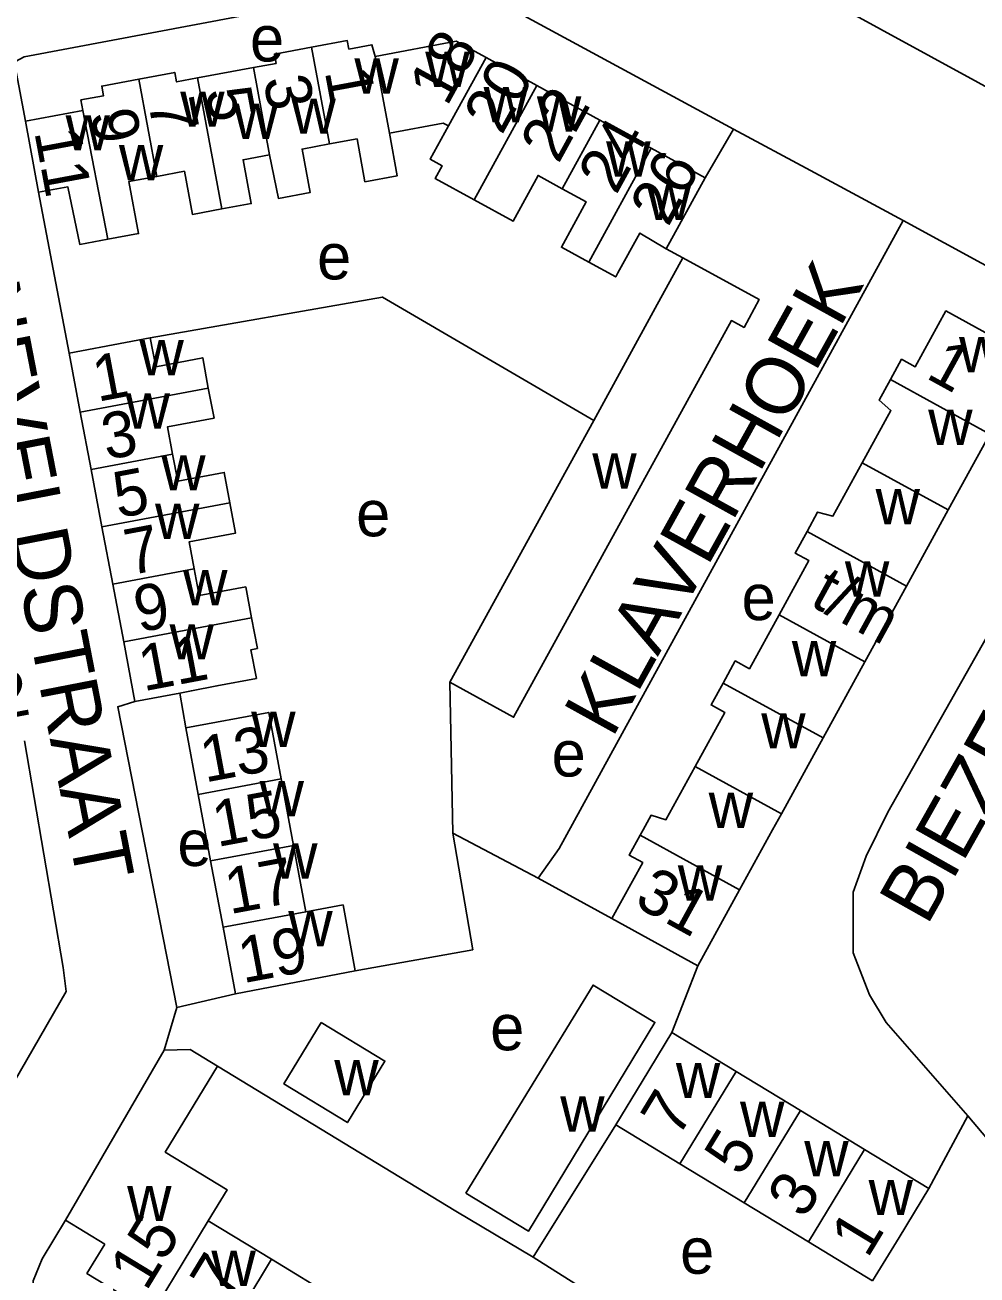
# Model space of a CAD drawing. Extents: x 158356 to 159894, y 383831 to 385260.
# Drawn here: x 158810.6 to 158893.5, y 383961.2 to 384070.1 of the extents above; entities that cross this region are included whole.
import ezdxf

# ---------------------------------------------------------------- set-up
doc = ezdxf.new("R2010")
doc.units = 0
for name, color, linetype in [('BLT_Basislijn', 7, 'Continuous'), ('BLT_Bebouwing', 7, 'Continuous'), ('BLT_Centroide', 7, 'Continuous'), ('BLT_Huisnummer', 7, 'Continuous'), ('BLT_Huisnummer_ tussenligend', 7, 'Continuous'), ('BLT_Huisnummer_reeks', 7, 'Continuous'), ('BLT_Onderverdeling_panden', 7, 'Continuous'), ('BLT_Straatnaam', 7, 'Continuous')]:
    doc.layers.add(name, color=color, linetype=linetype)

msp = doc.modelspace()

# ---------------------------------------------------------------- linework, layer by layer
at = {"layer": 'BLT_Basislijn'}
for p, q in [((158869.84, 384056.78), (158872.31, 384061.02)), ((158811.81, 384055.53), (158814.46, 384041.51)), ((158867.92, 384049.82), (158866.45, 384050.61)), ((158847.88, 383999.71), (158847.63, 384012.86)), ((158824.1, 384011.92), (158824.63, 384008.88)), ((158813.96, 383988.01), (158810.59, 384007.75)), ((158847.88, 383999.71), (158855.3, 383995.79)), ((158855.3, 383995.79), (158861.73, 383992.28)), ((158866.95, 383982.37), (158869.22, 383988.17)), ((158823.85, 383984.52), (158828.95, 383985.73)), ((158823.85, 383984.52), (158822.73, 383980.82)), ((158892.73, 383975.11), (158889.32, 383968.77)), ((158892.73, 383975.11), (158900.43, 383965.89)), ((158862.06, 383974.33), (158854.87, 383962.79)), ((158877.21, 383948.71), (158854.87, 383962.79))]:
    msp.add_line(p, q, dxfattribs=at)
for points in [[(158833.44, 384117.69), (158855.2, 384086.11), (158906.53, 384058.02)], [(158810.66, 384061.72), (158809.81, 384066.33), (158809.81, 384066.91), (158810.54, 384067.32), (158847.76, 384074.35)], [(158847.76, 384074.35), (158872.31, 384061.02)], [(158887.08, 384053.08), (158879.02, 384057.42), (158872.31, 384061.02)], [(158887.08, 384053.08), (158857.13, 383998.39), (158855.3, 383995.79)], [(158887.08, 384053.08), (158904.3, 384043.68), (158905.57, 384042.39), (158906.53, 384040.81), (158906.21, 384037.78), (158885.76, 384001.55), (158883.87, 383997.72), (158882.73, 383994.59), (158882.73, 383989.28), (158884.17, 383985.63), (158885.61, 383983.23), (158892.73, 383975.11)], [(158860.15, 384035.66), (158841.75, 384046.4), (158821.53, 384042.85)], [(158820.2, 384011.18), (158818.71, 384010.73), (158823.85, 383984.52)], [(158847.88, 383999.71), (158849.62, 383989.56), (158839.39, 383987.72)], [(158759.91, 383992.3), (158798.47, 383965.97), (158799.62, 383965.5), (158801.69, 383965.58), (158803.35, 383967.13), (158814.2, 383985.93), (158813.96, 383988.01)], [(158827.39, 383979.43), (158848.13, 383966.79), (158854.87, 383962.79)], [(158814.16, 383966.01), (158812.13, 383962.64), (158811.34, 383960.74), (158811.34, 383959.69), (158812.63, 383957.28), (158815.24, 383955.2), (158828.49, 383947.37), (158863.52, 383925.87)]]:
    msp.add_lwpolyline(points, dxfattribs=at)
at = {"layer": 'BLT_Bebouwing'}
for p, q in [((158850.77, 384067.26), (158855.2, 384064.82)), ((158825.65, 384065.48), (158830.53, 384066.38)), ((158855.2, 384064.82), (158860.68, 384061.81)), ((158810.66, 384061.72), (158815.66, 384062.65)), ((158860.68, 384061.81), (158865.14, 384059.36)), ((158811.81, 384055.53), (158810.66, 384061.72)), ((158865.14, 384059.36), (158869.84, 384056.78)), ((158869.84, 384056.78), (158866.45, 384050.61)), ((158815.43, 384036.37), (158814.46, 384041.51)), ((158816.38, 384031.38), (158815.43, 384036.37)), ((158860.15, 384035.66), (158847.63, 384012.86)), ((158894.65, 384034.47), (158891.02, 384027.86)), ((158817.33, 384026.38), (158816.38, 384031.38)), ((158891.02, 384027.86), (158887.39, 384021.24)), ((158818.27, 384021.39), (158817.33, 384026.38)), ((158819.22, 384016.37), (158818.27, 384021.39)), ((158887.39, 384021.24), (158883.75, 384014.63)), ((158820.2, 384011.18), (158819.22, 384016.37)), ((158883.75, 384014.63), (158880.12, 384008.01)), ((158824.1, 384011.92), (158820.2, 384011.18)), ((158825.71, 384003.09), (158824.63, 384008.88)), ((158880.12, 384008.01), (158876.49, 384001.4)), ((158832.93, 384004.44), (158834.01, 383998.65)), ((158825.71, 384003.09), (158826.79, 383997.31)), ((158834.01, 383998.65), (158835.09, 383992.86)), ((158827.87, 383991.52), (158826.79, 383997.31)), ((158872.85, 383994.78), (158869.22, 383988.17)), ((158869.22, 383988.17), (158861.73, 383992.28)), ((158828.95, 383985.73), (158827.87, 383991.52)), ((158839.39, 383987.72), (158828.95, 383985.73)), ((158866.95, 383982.37), (158872.55, 383978.97)), ((158822.73, 383980.82), (158814.16, 383966.01)), ((158872.55, 383978.97), (158878.14, 383975.57)), ((158878.14, 383975.57), (158883.73, 383972.17)), ((158867.66, 383970.93), (158862.06, 383974.33)), ((158883.73, 383972.17), (158889.32, 383968.77)), ((158873.25, 383967.53), (158867.66, 383970.93)), ((158878.84, 383964.13), (158873.25, 383967.53)), ((158814.16, 383966.01), (158817.58, 383963.93)), ((158826.59, 383965.95), (158832.09, 383962.61)), ((158884.43, 383960.73), (158878.84, 383964.13)), ((158832.09, 383962.61), (158837.69, 383959.2))]:
    msp.add_line(p, q, dxfattribs=at)
for points in [[(158835.58, 384068.16), (158838.69, 384068.74), (158838.83, 384068), (158840.83, 384068.38), (158841.11, 384067.36)], [(158841.11, 384067.36), (158848.18, 384068.68), (158850.77, 384067.26)], [(158830.53, 384066.38), (158832.49, 384066.75), (158832.34, 384067.56), (158835.58, 384068.16)], [(158815.66, 384062.65), (158815.49, 384063.57), (158817.47, 384063.93), (158817.31, 384064.78), (158820.53, 384065.37)], [(158820.53, 384065.37), (158823.67, 384065.96), (158823.82, 384065.14), (158825.65, 384065.48)], [(158842.36, 384060.67), (158843.04, 384056.97), (158840.23, 384056.45), (158839.54, 384060.18), (158837.14, 384059.74)], [(158847.51, 384061.31), (158847.05, 384061.55), (158842.36, 384060.67)], [(158849.74, 384054.86), (158846.35, 384056.72), (158846.96, 384057.83), (158845.92, 384058.4), (158847.51, 384061.31)], [(158837.14, 384059.74), (158834.75, 384059.29), (158835.46, 384055.51), (158832.69, 384054.99), (158831.93, 384058.79)], [(158831.93, 384058.79), (158829.61, 384058.36), (158830.32, 384054.55), (158827.76, 384054.08)], [(158822.1, 384056.91), (158819.68, 384056.47), (158820.52, 384051.93), (158817.84, 384051.44)], [(158827.76, 384054.08), (158825.21, 384053.6), (158824.51, 384057.36), (158822.1, 384056.91)], [(158857.41, 384055.84), (158855.31, 384056.99), (158853.13, 384053.01), (158849.74, 384054.86)], [(158817.84, 384051.44), (158815.4, 384050.99), (158814.36, 384056), (158811.81, 384055.53)], [(158859.71, 384049.45), (158857.34, 384050.74), (158859.5, 384054.69), (158857.41, 384055.84)], [(158866.45, 384050.61), (158864.17, 384051.97), (158862.26, 384048.5), (158862.07, 384048.15), (158859.71, 384049.45)], [(158847.63, 384012.86), (158848.79, 384012.22), (158853.17, 384009.81), (158872.13, 384044.36), (158873.24, 384043.76), (158874.56, 384046.18), (158867.92, 384049.82)], [(158867.92, 384049.82), (158865.51, 384045.44), (158860.15, 384035.66)], [(158885.99, 384039.23), (158886.96, 384040.99), (158888.14, 384040.34), (158890.81, 384045.19), (158898.29, 384041.08), (158894.65, 384034.47)], [(158814.46, 384041.51), (158819.37, 384042.44), (158821.53, 384042.85)], [(158821.53, 384042.85), (158822.01, 384040.34), (158826.1, 384041.11), (158826.59, 384038.48)], [(158883.52, 384031.98), (158886.02, 384036.51), (158885, 384037.42), (158885.99, 384039.23)], [(158826.59, 384038.48), (158827.09, 384035.86), (158823.03, 384035.09), (158823.48, 384032.72)], [(158823.48, 384032.72), (158823.92, 384030.36), (158827.97, 384031.13), (158828.47, 384028.49)], [(158878.72, 384026), (158879.63, 384027.67), (158880.97, 384027.33), (158883.52, 384031.98)], [(158828.47, 384028.49), (158828.97, 384025.85), (158824.91, 384025.08), (158825.36, 384022.74)], [(158876.29, 384018.73), (158878.88, 384023.46), (158877.68, 384024.11), (158878.72, 384026)], [(158825.36, 384022.74), (158825.8, 384020.4), (158829.85, 384021.16), (158830.36, 384018.48)], [(158830.36, 384018.48), (158830.87, 384015.8), (158830.3, 384015.69), (158830.77, 384013.19), (158827.34, 384012.54), (158825.12, 384012.12), (158824.1, 384011.92)], [(158871.42, 384012.79), (158872.47, 384014.71), (158873.7, 384014.03), (158876.29, 384018.73)], [(158868.99, 384005.52), (158871.57, 384010.22), (158870.37, 384010.88), (158871.42, 384012.79)], [(158824.63, 384008.88), (158831.85, 384010.23), (158832.93, 384004.44)], [(158864.19, 383999.54), (158864.44, 384000), (158865.14, 384001.27), (158866.44, 384000.89), (158868.99, 384005.52)], [(158876.49, 384001.4), (158875.72, 384000), (158872.85, 383994.78)], [(158861.73, 383992.28), (158864.41, 383997.15), (158863.22, 383997.8), (158864.19, 383999.54)], [(158835.09, 383992.86), (158838.32, 383993.47), (158839.39, 383987.72)], [(158849, 383968.37), (158854.46, 383965.05), (158865.47, 383983.24), (158860.09, 383986.49), (158849, 383968.37)], [(158836.42, 383983.23), (158833.17, 383977.88), (158838.7, 383974.51), (158841.96, 383979.87), (158836.42, 383983.23)], [(158862.06, 383974.33), (158864.36, 383978.1), (158866.95, 383982.37)], [(158827.39, 383979.43), (158825, 383980.89), (158822.73, 383980.82)], [(158827.39, 383979.43), (158822.84, 383971.94), (158828.23, 383968.66), (158826.59, 383965.95)], [(158889.32, 383968.77), (158886.73, 383964.5), (158884.43, 383960.73)], [(158821.7, 383957.91), (158816.02, 383961.37), (158817.58, 383963.93)]]:
    msp.add_lwpolyline(points, dxfattribs=at)
at = {"layer": 'BLT_Onderverdeling_panden'}
for p, q in [((158837.14, 384059.74), (158835.58, 384068.16)), ((158842.36, 384060.67), (158841.11, 384067.36)), ((158847.51, 384061.31), (158850.77, 384067.26)), ((158831.93, 384058.79), (158830.53, 384066.38)), ((158822.1, 384056.91), (158820.53, 384065.37)), ((158827.76, 384054.08), (158825.65, 384065.48)), ((158849.74, 384054.86), (158855.2, 384064.82)), ((158817.84, 384051.44), (158815.66, 384062.65)), ((158857.41, 384055.84), (158860.68, 384061.81)), ((158859.71, 384049.45), (158865.14, 384059.36)), ((158894.65, 384034.47), (158885.99, 384039.23)), ((158826.59, 384038.48), (158815.43, 384036.37)), ((158823.48, 384032.72), (158816.38, 384031.38)), ((158891.02, 384027.86), (158883.52, 384031.98)), ((158828.47, 384028.49), (158817.33, 384026.38)), ((158887.39, 384021.24), (158878.72, 384026)), ((158825.36, 384022.74), (158818.27, 384021.39)), ((158830.36, 384018.48), (158819.22, 384016.37)), ((158883.75, 384014.63), (158876.29, 384018.73)), ((158880.12, 384008.01), (158871.42, 384012.79)), ((158876.49, 384001.4), (158868.99, 384005.52)), ((158825.71, 384003.09), (158832.93, 384004.44)), ((158826.79, 383997.31), (158834.01, 383998.65)), ((158872.85, 383994.78), (158864.19, 383999.54)), ((158827.87, 383991.52), (158835.09, 383992.86)), ((158867.66, 383970.93), (158872.55, 383978.97)), ((158873.25, 383967.53), (158878.14, 383975.57)), ((158878.84, 383964.13), (158883.73, 383972.17)), ((158821.7, 383957.91), (158826.59, 383965.95)), ((158827.21, 383954.57), (158832.09, 383962.61))]:
    msp.add_line(p, q, dxfattribs=at)

# ---------------------------------------------------------------- texts
at = {"layer": 'BLT_Centroide'}
for s, p in [('e', (158830.22, 384066.92)), ('w', (158839.31, 384064.11)), ('w', (158845.48, 384064.69)), ('w', (158824.14, 384061.23)), ('w', (158850.56, 384061.61)), ('w', (158828.8, 384060.17)), ('w', (158833.83, 384060.62)), ('w', (158855.2, 384060.81)), ('w', (158814.16, 384059.17)), ('w', (158818.8, 384056.58)), ('w', (158861.23, 384056.88)), ('w', (158864.77, 384053.11)), ('e', (158836.06, 384047.94)), ('w', (158820.59, 384039.59)), ('w', (158891.96, 384039.84)), ('w', (158819.38, 384034.94)), ('w', (158889.27, 384033.53)), ('w', (158822.49, 384029.56)), ('w', (158860.02, 384029.73)), ('w', (158884.69, 384026.62)), ('w', (158821.95, 384025.34)), ('e', (158839.46, 384025.57)), ('w', (158824.39, 384019.56)), ('w', (158882.02, 384020.31)), ('e', (158873.02, 384018.27)), ('w', (158823.21, 384014.84)), ('w', (158877.4, 384013.38)), ('w', (158830.32, 384007.22)), ('w', (158874.73, 384007.09)), ('e', (158856.48, 384004.65)), ('w', (158831.05, 384001.19)), ('w', (158870.16, 384000.16)), ('e', (158823.9, 383996.86)), ('w', (158832.23, 383995.75)), ('w', (158867.47, 383993.84)), ('w', (158833.55, 383989.87)), ('e', (158851.13, 383980.81)), ('w', (158837.56, 383976.88)), ('w', (158867.3, 383976.64)), ('w', (158857.23, 383973.73)), ('w', (158872.89, 383973.25)), ('w', (158878.48, 383969.84)), ('w', (158884.08, 383966.45)), ('w', (158819.52, 383965.93)), ('e', (158867.67, 383961.35)), ('w', (158826.86, 383960.28))]:
    msp.add_text(s, height=4, dxfattribs=at).set_placement(p)
at = {"layer": 'BLT_Huisnummer'}
for s, rotation, p in [('18', 61.2845, (158847.36, 384062.91)), ('1', 280.5098, (158836.72, 384066.05)), ('5', 280.5098, (158826.31, 384064.37)), ('22', 61.2845, (158857.07, 384057.93)), ('11', 280.5098, (158811.43, 384060.79)), ('26', 61.2845, (158866.62, 384052.43)), ('1', 10.7298, (158816.94, 384037.27)), ('5', 10.7298, (158818.73, 384027.14)), ('11', 10.7298, (158820.94, 384012.06)), ('12', 10.7217, (158805.39, 384008.99)), ('13', 10.5608, (158826.3, 384004.12)), ('19', 10.5608, (158829.61, 383986.64)), ('7', 58.7002, (158867.47, 383973.08)), ('15', 58.7061, (158821.18, 383959.74)), ('1', 58.7002, (158883.98, 383962.61))]:
    msp.add_text(s, height=4, rotation=rotation, dxfattribs=at).set_placement(p)
at = {"layer": 'BLT_Huisnummer_ tussenligend'}
for s, rotation, p in [('20', 61.2845, (158852.14, 384060.43)), ('3', 280.5098, (158831.37, 384065.38)), ('7', 280.5098, (158821.34, 384063.39)), ('9', 280.5098, (158816.31, 384062.45)), ('24', 61.2845, (158862.1, 384055.22)), ('3', 10.7298, (158817.72, 384032.21)), ('7', 10.7298, (158819.71, 384022.16)), ('9', 10.7298, (158820.54, 384017.19)), ('15', 10.5608, (158827.36, 383998.5)), ('17', 10.5608, (158828.45, 383992.65)), ('5', 58.7002, (158872.98, 383969.71)), ('3', 58.7002, (158878.48, 383966.02)), ('17', 58.7061, (158826.68, 383956.33))]:
    msp.add_text(s, height=4, rotation=rotation, dxfattribs=at).set_placement(p)
at = {"layer": 'BLT_Huisnummer_reeks'}
for s, rotation, p in [('1', 331.218, (158888.96, 384039.41)), ('t/m', 331.2191, (158878.84, 384019.62)), ('31', 331.2165, (158863.55, 383993.47))]:
    msp.add_text(s, height=4, rotation=rotation, dxfattribs=at).set_placement(p)
at = {"layer": 'BLT_Straatnaam'}
for s, height, rotation, p in [('BARNEVELDSTRAAT', 4.9999, 281, (158802.49, 384060.84)), ('KLAVERHOEK', 5, 61, (158861.76, 384007.9)), ('BIEZENWEG', 5, 60.6043, (158889.16, 383991.57))]:
    msp.add_text(s, height=height, rotation=rotation, dxfattribs=at).set_placement(p)

doc.saveas('drawing.dxf')
